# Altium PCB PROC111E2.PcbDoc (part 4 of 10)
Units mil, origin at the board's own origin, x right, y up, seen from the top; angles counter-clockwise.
Board outline 7700 x 2300 mil, 6 copper layers (Top Layer, GND 1, SIG 1, SIG 2, GND 2, Bottom Layer), stack 78.711 mil thick; 767 components, 596 nets, 2755 pads, 1578 vias.
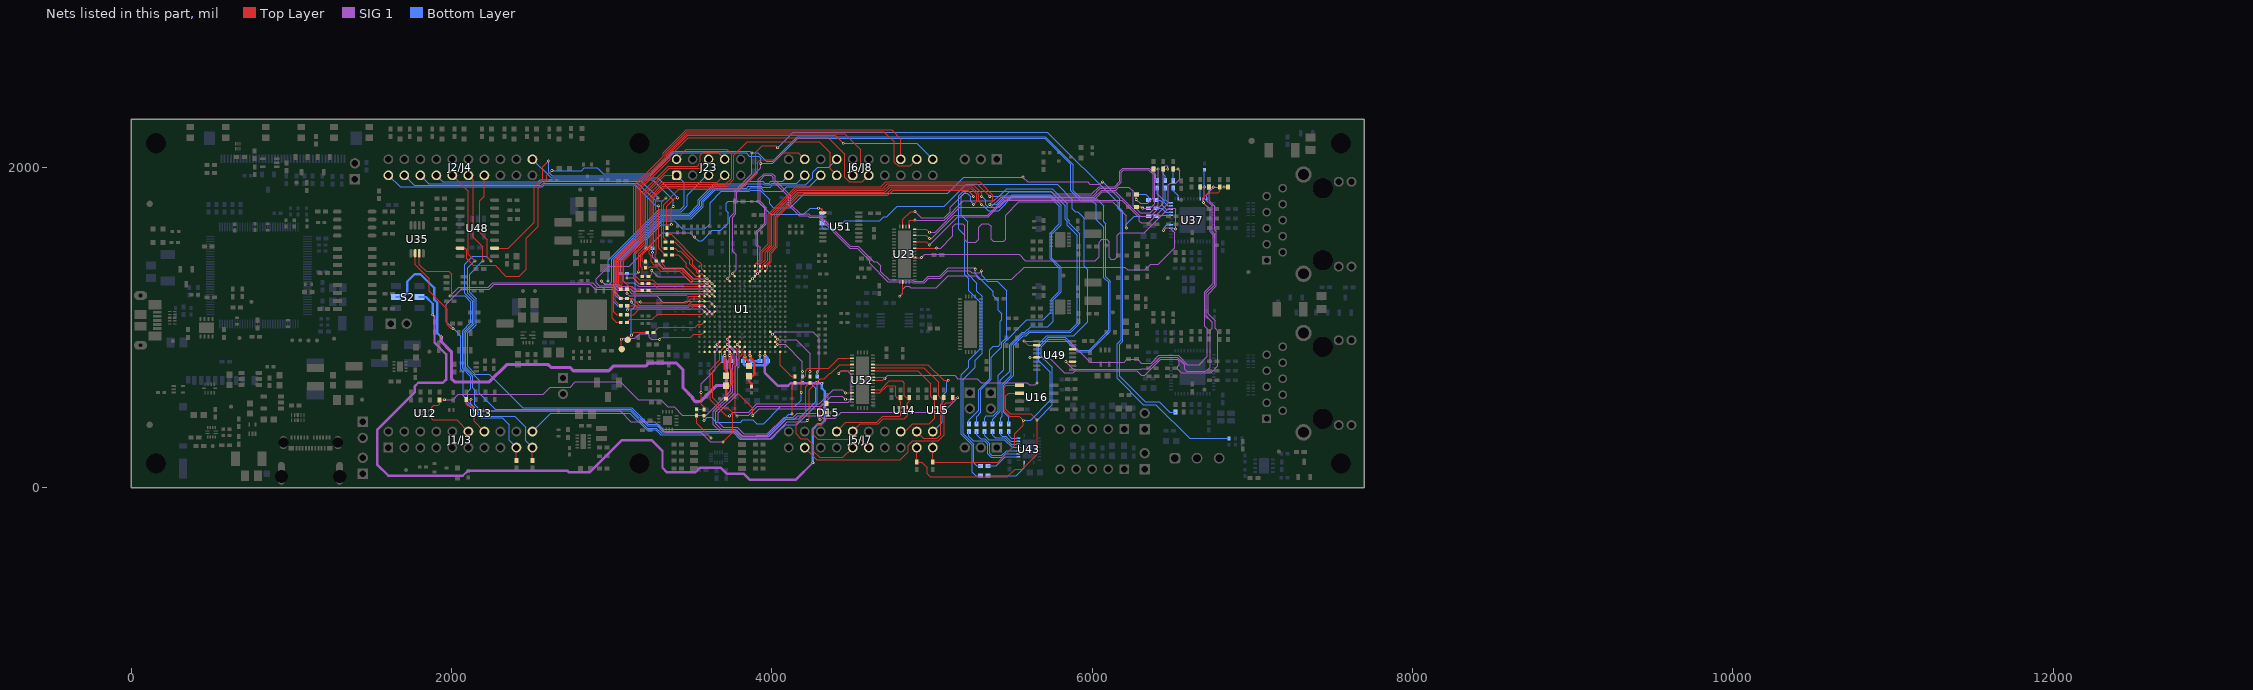
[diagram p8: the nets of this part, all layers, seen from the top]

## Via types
v1: diameter 18, hole 8, Top Layer to Bottom Layer, tented both sides, 1474 vias
v2: diameter 19.68, hole 7.87, Top Layer to Bottom Layer, tented both sides, 104 vias

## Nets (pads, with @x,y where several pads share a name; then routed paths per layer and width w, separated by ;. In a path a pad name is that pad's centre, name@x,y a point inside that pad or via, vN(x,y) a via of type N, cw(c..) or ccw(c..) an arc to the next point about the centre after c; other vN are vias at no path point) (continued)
AM263_ADC2_AIN2: U1.U10 U52.27 | length 1481.7
  Top Layer w5.3: U1.U10@3830.6,878.86 3813.63,861.89 3813.63,832.56 3785,803.94 3785,590 3880,495 v1(3880,450.85) ; v1(4417.1,713.38) 4432.77,729.06 U52.27@4500.04,729.06
  SIG 1 w4.75: v1(3880,450.85) 3921.63,492.49 4317.74,492.49 4357.02,531.77 4477.64,531.77 4495.75,549.88 4495.75,703.31 4470,729.06 4432.77,729.06 v1(4417.1,713.38)
AM263_ADC2_AIN2_SDFM0_CLK2: C93.1 J5/J7.68 U15.2 U15.9 U52.12 | length 879.5
  Top Layer w5.3: U52.12@4629.96,729.06 4909.46,729.06 4990,648.51 4990,570 4998.33,561.67 C93.1@5017.97,561.67 5015.48,559.18 5015.48,500.94 U15.9@5015.72,500.69 U15.2@5015.72,467.82 5015.72,432.26 4983.46,400 4879.37,400 4829.37,350 J5/J7.68@4804.17,350
AM263_ADC2_AIN3: C95.1 J5/J7.42 U1.T9 U15.5 U15.6 | length 3539.7
  Top Layer w5.3: J5/J7.42@4204.17,250 4280.97,173.2 4801.74,173.2 4852.06,223.52 4852.06,265 4880.13,293.06 5039.39,293.06 5074.77,328.45 U15.5@5074.77,467.82 ; v1(5160,561.03) 5159.36,561.67 C95.1@5128.54,561.67 5128.54,542.46 5114.41,528.33 5085.81,528.33 5074.77,517.29 U15.6@5074.77,500.69 ; U15.5@5074.77,467.82 U15.6@5074.77,500.69 ; U15.5@5074.77,467.82 U15.6@5074.77,500.69
  Top Layer w10: v1(3783.35,894.61) U1.T9@3799.1,910.35
  SIG 1 w4.75: v1(3783.35,894.61) 3794.9,883.06 3794.9,754.51 3785,744.61 3785,587.4 3665.68,468.08 3665.68,406.97 3696.4,376.25 3781.88,376.25 3823.5,334.63 3971.9,334.63 4077.01,439.74 4132.97,439.74 4157.22,463.99 4287.17,463.99 4318,433.16 4393.5,433.16 4431.09,470.75 5069.72,470.75 v1(5160,561.03)
AM263_ADC2_AIN4: U1.V9
AM263_ADC2_AIN5: U1.T8
AM263_ADC3_AIN0: C75.1 J1/J3.26 U1.U7 U12.5 U12.6 | length 2730.5
  Top Layer w5.3: v1(1954,548.33) C75.1@1924,548.33 1924,520.24 1916.62,512.86 1887.02,512.86 1874.37,500.2 U12.6@1874.37,480.91 U12.5@1874.37,448.04 1874.37,428.47 1880,422.84 2031.34,422.84 J1/J3.26@2104.17,350
  Top Layer w10: v1(3720.36,863.11) U1.U7@3736.11,878.86
  SIG 1 w4: v1@3720.36,862.49 v1(3720.36,863.11)
  SIG 1 w4.75: v1(1954,548.33) 2007.95,548.33 2041.97,582.35 2570,582.35 2615.14,627.49 2739.16,627.49 2771.67,660 3053.54,660 3163.53,550.01 3304.97,550.01 3350.45,504.53 3389.28,504.53 3441.06,452.75 3589.89,452.75 3741.83,604.69 3741.83,786.42 3751.48,796.07 3751.48,831.37 v1@3720.36,862.49
AM263_ADC3_AIN1: U1.U8 U52.36 | length 1226.9
  Top Layer w5.3: U1.U8@3767.61,878.86 3782.13,864.33 3782.13,829.46 3769.58,816.91 3769.58,458.43 v1(3781.85,446.17) ; v1(4458.39,551.89) U52.36@4500.04,551.89
  SIG 1 w4.75: v1(3781.85,446.17) 3788.43,452.75 3854.68,452.75 3908.66,506.74 4306.74,506.74 4371.14,571.14 4439.14,571.14 v1(4458.39,551.89)
AM263_ADC3_AIN1_MCAN1_TX: C86.1 J5/J7.64 U14.2 U14.9 U52.5 | length 812.1
  Top Layer w5.3: J5/J7.64@4404.17,350 4462.03,407.86 4653.57,407.86 4690.71,445 4799.14,445 4805.31,451.17 U14.2@4805.31,467.68 U14.9@4805.31,500.55 4805.31,533.2 4802.11,536.4 C86.1@4802.11,561.53 4780.42,561.53 4772.38,569.58 4772.38,630 4765.84,636.54 4719.02,636.54 4673.74,591.26 U52.5@4629.96,591.26
AM263_ADC3_AIN2: U1.T7 U52.25 | length 1796
  Top Layer w5.3: v1(4220,419.26) 4231.5,430.75 4231.5,611.09 4300.41,680 4326.38,680 4359.76,713.38 4367,713.38 4422.04,768.43 U52.25@4500.04,768.43
  Top Layer w10: v1(3720.36,894.61) U1.T7@3736.11,910.35
  SIG 1 w4.75: v1(3720.36,894.61) 3720.36,893.05 3765.73,847.67 3765.73,776.62 3756.08,766.97 3756.08,598.79 3634.18,476.89 3634.18,393.18 3679.62,347.75 3770.07,347.75 3811.7,306.13 3989.63,306.13 4094.74,411.24 4211.98,411.24 v1(4220,419.26)
AM263_ADC3_AIN2_SDFM0_D3: C94.1 J5/J7.69 U15.4 U15.7 U52.13 | length 984.4
  Top Layer w5.3: U52.13@4629.96,748.74 4948.18,748.74 5040.31,656.61 5040.31,573.23 5051.87,561.67 C94.1@5073,561.67 5073,538 5055.09,520.09 U15.7@5055.09,500.69 U15.4@5055.09,467.82 5055.09,331.25 5032.8,308.96 4945.21,308.96 J5/J7.69@4904.17,350
AM263_ADC3_AIN3: C96.1 D15.2 J5/J7.46 U1.R7 | length 2133.9
  Top Layer w5.3: v1(4300.31,423.62) 4300.31,508.74 4317.89,526.31 C96.1@4339.72,526.31 4339.72,467.6 D15.2@4338.78,466.66 4338.78,423.78 4310,395 4282.16,395 4257.41,370.25 4257.41,329.77 4284.26,302.93 4551.24,302.93 J5/J7.46@4604.17,250
  Top Layer w10: v1(3720.36,926.1) U1.R7@3736.11,941.85
  SIG 1 w4: v1(3720.36,926.1) 3736.86,909.61 3736.86,888.39 3779.98,845.27
  SIG 1 w4.75: 3779.98,845.27 3779.98,764.98 3770.33,755.33 3770.33,592.89 3650,472.55 3650,397.52 3685.52,362 3775.98,362 3817.6,320.38 3983.73,320.38 4088.84,425.49 4138.88,425.49 4162.23,448.84 4275.09,448.84 v1(4300.31,423.62)
AM263_ADC3_AIN4: U1.V8
AM263_ADC3_AIN5: U1.U9
AM263_ADC4_AIN0: C81.1 J1/J3.27 U1.U6 U13.1 U13.10 | length 2712.5
  Top Layer w5.3: v1@2120,548.85 C81.1@2090,548.85 2090,520 2098.65,511.35 2124.65,511.35 2140.63,495.36 U13.10@2140.63,481.44 U13.1@2140.63,448.56 2140.63,413.54 J1/J3.27@2204.17,350 ; v1(3694.17,285) 3755.86,346.68 3755.86,466.58 3722.44,500 3690,500 3628.99,561.01 3628.99,727.74 3687.64,786.39 3687.64,861.89 U1.U6@3704.61,878.86
  SIG 1 w4.75: v1(2120,548.85) 2120,522.52 2163.5,479.02 3050.98,479.02 3118.98,411.02 3267.48,411.02 3334,344.5 3555,344.5 3614.5,285 v1(3694.17,285)
AM263_ADC4_AIN1: U1.V5 U52.34 | length 1326.7
  Top Layer w5.3: U1.V5@3673.12,847.36 3673.12,797.41 3613.09,737.38 3613.09,549.79 3714.78,448.1 v1(3735,448.1) ; v1(4458.39,591.26) U52.34@4500.04,591.26
  SIG 1 w4.75: v1(3735,448.1) 3758.61,471.71 3853.48,471.71 3906.06,524.29 4295.27,524.29 4381.49,610.51 4439.14,610.51 v1(4458.39,591.26)
AM263_ADC4_AIN1_LIN1_RXD: C87.1 J5/J7.65 U14.4 U14.7 U52.6 | length 837
  Top Layer w5.3: J5/J7.65@4504.17,350 4551.43,397.26 4662,397.26 4696.12,431.38 4826.04,431.38 4844.69,450.03 U14.4@4844.69,467.68 U14.7@4844.69,500.55 4844.69,527.99 4856.7,540 C87.1@4856.7,561.53 4838.47,561.53 4827.2,572.8 4827.2,651.1 4812.48,665.82 4732.61,665.82 4677.73,610.94 U52.6@4629.96,610.94
AM263_ADC4_AIN2: U1.V4
AM263_ADC4_AIN3: U1.U5
AM263_ADC4_AIN4: U1.V3
AM263_ADC4_AIN5: U1.U4
AM263_ADC_CAL0: U1.U16
AM263_ADC_CAL1: U1.T15
AM263_ADC_VREFHI_G01: C77.1 C79.1 C80.1 S2.2 U1.V10 U1.V14 | length 5924.9
  Top Layer w15: U1.V10@3830.6,847.36 3831.11,846.85 v1(3831.11,816.77) 3831.11,810.33 3830.6,809.82 3855,785.41 C77.1@3855,758.87 ; v1(3956.58,825) U1.V14@3956.58,847.36
  SIG 1 w15: v1(1881.26,1079.09) 1892.09,1068.26 1892.09,905.2 1964.73,832.57 1964.73,674.26 1944.82,654.35 1790.45,654.35 1770,633.9 1770,596.59 1533.7,360.28 1533.7,144.46 1604.73,73.43 2068.73,73.43 2099.68,104.37 2723.63,104.37 2733.12,94.88 2860.51,94.88 3060.41,294.78 3250,294.78 3316.5,228.28 3316.5,123.5 3344.87,95.13 3520.66,95.13 3550.31,124.78 3678.51,124.78 3716.07,87.22 3822.14,87.22 3859.35,50 4149.88,50 4254.88,155 v1(4255,155) ; v1(3956.58,825) 3956.01,824.43 3956.01,822.3 3955.63,821.92 3955.63,719.49 3956.05,719.06 3956.05,716.42 4035.38,637.09 4101.11,637.09 4115.3,651.28 v1(4311.54,651.28)
  Bottom Layer w15: S2.2@1797.54,1190 1839.19,1190 1881.26,1147.93 v1(1881.26,1079.09) ; v1(3831.11,816.77) 3823.14,808.8 3823.14,769.23 3829.62,762.75 3958.56,762.75 3972.24,776.43 C80.1@3972.24,789.94 3972.24,809.34 v1(3956.58,825) ; v1(4255,155) 4255,365.72 4285.17,395.89 4307.05,395.89 4329.69,418.53 4329.69,601.57 4311.54,619.71 v1(4311.54,651.28)
AM263_ADC_VREFHI_G2: C76.1 C78.1 S2.5 U1.V6 | length 3381
  Top Layer w15: U1.V6@3704.61,847.36 v1(3704.61,825) 3704.61,742.32 3713.32,733.62 3713.32,698.14 C76.1@3713.17,698
  SIG 1 w8: 3704.49,800.8 3707.05,798.24 ; v1@3704.49,824.87 v1(3704.61,825)
  SIG 1 w20: v1(1935,940) 1935,912.11 1998.13,848.98 1998.13,680.65 2018.77,660 2234.9,660 2342.91,768.02 2602.89,768.02 2620.91,750 2739.93,750 2759.93,730 2979.51,730 3008.2,758.68 3210.94,758.68 3230.34,778.09 3401.52,778.09 3444.13,735.48 3444.13,622.47 3504.51,562.09 3504.51,552.94 3520.25,537.2 3550.76,537.2 3650.66,637.09 3700.33,637.09 3715.62,652.38 3715.62,789.67 3707.05,798.24 ; 3704.49,800.8 v1@3704.49,824.87
  Bottom Layer w15: S2.5@1651.87,1190 1697.96,1190 1721.8,1213.85 1721.8,1286.8 1767.62,1332.62 1805,1332.62 1890.03,1247.59 1890.03,1174.7 1910,1154.73 1910,965 v1(1935,940) ; C78.1@3696.74,789.94 3696.74,817.13 v1(3704.61,825)
AM263_ADC_VREFLO_G01: C77.2 C79.2 C80.2 R44.2 U1.V11 U1.V13 | length 413.8
  Top Layer w4: v1(3925.09,825) U1.V13@3925.09,847.36
  Top Layer w15: U1.V11@3862.09,847.36 v1(3862.09,825) 3862.67,824.43 3862.67,812.33 3889.07,785.92 3889.07,707.15 3877.8,695.88 C77.2@3855,695.88 3855,666.5 3872.63,648.88 R44.2@3872.63,631.2
  Bottom Layer w15: v1(3862.09,825) 3862.09,824.19 3868.43,817.85 C79.2@3868.43,789.94 C80.2@3925,789.94 3925,824.91 v1(3925.09,825)
AM263_ADC_VREFLO_G2: C76.2 C78.2 R307.2 U1.V7 | length 362.5
  Top Layer w15: R307.2@3713.62,555 3713.17,555.45 C76.2@3713.17,635.01 3737.59,635.01 3748.83,646.26 3748.83,733.91 3736.11,746.64 v1@3736.11,822.29 ; v1(3736.11,825) U1.V7@3736.11,847.36
  Bottom Layer w15: v1(3736.11,825) 3743.98,817.13 C78.2@3743.98,789.94
AM263_ATESTV0: U1.U3
AM263_ATESTV1: U1.V2
AM263_BP_MUX_SEL_GPIO63: R298.2 R300.2 U1.G4 U51.1 U52.9 U52.10 | length 7040.3
  Top Layer w5.3: v1(4291.03,1744.24) 4306.84,1744.24 4317.8,1733.28 U51.1@4317.8,1717.48 ; U52.9@4629.96,670 4693.01,670 v1(4705,681.99) 4697.31,689.68 U52.10@4629.96,689.68
  Top Layer w10: v1(3625.87,1209.57) U1.G4@3641.62,1193.82
  SIG 1 w4: 3518.68,1226.06 3609.38,1226.06 v1(3625.87,1209.57)
  SIG 1 w4.75: v1(3515.64,1564.46) 3488.69,1591.41 3317.97,1591.41 3109.37,1382.8 2979.62,1382.8 2902.31,1305.49 2902.31,1278.83 2921.14,1260 3024.5,1260 3042.5,1242 3116.39,1242 3132.32,1226.06 3518.68,1226.06
  SIG 1 w5.3: v1(4705,681.99) 4723.17,700.16 5141.38,700.16 5161.5,680.04 5281.04,680.04 5305.58,655.5 5592.71,655.5 5605.21,643 5644.31,643 v1(5654.39,653.09)
  Bottom Layer w5.3: v1(3515.64,1564.46) 3538.74,1541.35 3563.03,1541.35 3627.8,1606.12 3680.51,1606.12 3726.52,1652.14 3726.52,1715.86 3713.62,1728.77 3713.62,1775.16 3725.58,1787.12 3911.05,1787.12 3991.69,1706.48 4199.68,1706.48 4237.44,1744.24 v1(4291.03,1744.24) 4301.08,1744.24 4312.89,1732.43 R298.2@4312.89,1715.49 R300.2@4312.89,1652.52 4312.89,1626.91 4323,1616.79 4405.75,1616.79 4453.96,1665 4672.04,1665 4697.54,1690.5 4717.5,1690.5 4783.54,1756.54 5075.54,1756.54 5212,1893 5782.5,1893 5876.5,1799 5876.5,1741.5 5894,1724 5908.74,1724 5951,1681.74 5951,1383.57 5972.85,1361.72 5972.85,1035.35 5885.7,948.2 5714.61,948.2 5655,888.59 5655,653.69 v1(5654.39,653.09)
AM263_CAN_STB_GPIO51: R248.2 U1.D1 | length 6072.1
  Top Layer w4: 3515.64,1288.31 U1.D1@3547.13,1288.31
  Top Layer w5.3: 3515.64,1288.31 3507.89,1288.31 3435.14,1361.06 3322.44,1361.06 3291,1392.5 3263,1392.5 3246.28,1409.22 3246.28,1447.41 3234.85,1458.85 3234.85,1478.14 3261.6,1504.89 3261.6,1810.22 3323.68,1872.3 3801.74,1872.3 3899.52,1970.08 3899.52,2094.24 3940.28,2135 4022.68,2135 v1(4035.32,2122.36)
  Bottom Layer w5.3: v1(4035.32,2122.36) 4132.97,2220 5720,2220 6161.25,1778.75 6161.25,1740.07 6179.88,1721.45 6179.88,922.38 6155,897.5 6155,683.66 6320,518.66 6397.07,518.66 6608.49,307.24 R248.2@6855,307.24
AM263_CLKOUT0: R4.2 R118.1 TP1.1 | length 5760.5
  Top Layer w5.3: TP1.1@3098.87,922.75 3098.87,928.07 v1(3122.32,951.52) 3139.85,969.06 R4.2@3221.22,969.06
  SIG 1 w4.75: v1(5567.49,1938.61) 5596.85,1909.25 5970.75,1909.25 5984.25,1895.75 6051.33,1895.75 v1(6065,1909.42)
  Bottom Layer w5.3: v1(3122.32,951.52) 3122.32,1108.82 3144.52,1131.02 3144.52,1491.6 3317.93,1665 3389.12,1665 3439.12,1615 3580,1615 3613.9,1648.9 3613.9,1778.89 3684.53,1849.52 3858.86,1849.52 3867.31,1857.97 3925.21,1857.97 3985,1798.18 3985,1773.13 4009.25,1748.88 4114.83,1748.88 4204.88,1838.92 5097.92,1838.92 5197.61,1938.61 v1(5567.49,1938.61) ; v1(6065,1909.42) 6171.85,1802.57 6171.85,1744.46 6190.48,1725.84 6190.48,912.98 6171.85,894.35 6171.85,695.04 6330,536.89 6417.03,536.89 6482.54,471.38 R118.1@6520,471.38
AM263_CLKOUT0_R: R4.1 U1.M2 | length 345.9
  Top Layer w4: 3539.45,1020.59 3562.88,1020.59 U1.M2@3578.63,1036.34
  Top Layer w5.3: R4.1@3260.59,969.06 3293.06,1001.54 3520.39,1001.54 3539.45,1020.59
AM263_DAC_OUT1: J1/J3.30 R45.1 | length 1403.7
  Top Layer w5.3: R45.1@3528.72,450.24 3528.72,400.34 v1(3618.83,310.23)
  Bottom Layer w5.3: J1/J3.30@2504.17,350 2619.17,465 3112.73,465 3216.45,361.28 3273.73,361.28 3304.51,330.5 3598.56,330.5 v1(3618.83,310.23)
AM263_DAC_OUT2: R3.1 U52.23 | length 1253.4
  Top Layer w5.3: v1(3575.19,418.7) R3.1@3575.19,448.84 ; v1(4182.78,594.53) 4181.82,595.49 4181.82,670.64 4209.52,698.35 4209.52,729.88 4223.55,743.91 4353.02,743.91 4416.91,807.8 U52.23@4500.04,807.8
  Bottom Layer w5.3: v1(3575.19,418.7) 3594.71,438.22 3622.55,438.22 3651.67,409.1 3803.38,409.1 3818.8,424.52 3880.9,424.52 3905.95,399.46 3948.02,399.46 4054.9,506.35 4142.26,506.35 4182.08,546.17 4182.08,593.83 v1(4182.78,594.53)
AM263_DAC_OUT2_SDFM0_CLK3: J5/J7.70 U52.14 | length 871.6
  Top Layer w5.3: U52.14@4629.96,768.43 4973.69,768.43 5071.52,670.59 v1(5100.56,670.59)
  Bottom Layer w5.3: J5/J7.70@5004.17,350 5063.33,409.15 5063.33,573.33 5092.52,602.52 5092.52,661.13 5100.56,669.16 v1(5100.56,670.59)
AM263_DAC_OUT_R: R3.2 R45.2 U1.T5 | length 523.2
  Top Layer w5.3: R45.2@3528.72,489.61 3573.8,489.61 R3.2@3574.55,488.85 ; v1(3557.81,594.15) 3557.81,521.62 3574.55,504.87 R3.2@3574.55,488.85 ; R3.2@3575.19,488.21 R3.2@3574.55,488.85
  Top Layer w10: v1(3657.37,894.61) U1.T5@3673.12,910.35
  SIG 1 w4: 3645,815.87 3645,848.34 3657.37,860.71 v1(3657.37,894.61)
  SIG 1 w4.75: v1(3557.81,594.15) 3557.81,649.18 3645,736.37 3645,815.87
AM263_EPWM0_A: J2/J4.11 R46.1 | length 1229.8
  Top Layer w5.3: R46.1@3344.16,1620.17 3344.16,1756.66 3396.77,1809.27 v1(3410.06,1809.27)
  Bottom Layer w5.3: J2/J4.11@2504.17,2050 2620.48,1933.69 3285.64,1933.69 v1(3410.06,1809.27)
AM263_EPWM0_A_R: R46.2 U1.B2 | length 343.2
  Top Layer w4: 3536.77,1414.29 3537.52,1413.54 3539.53,1413.54 3547.44,1405.64 3547.58,1405.64 3562.88,1390.34 3562.88,1367.05 U1.B2@3578.63,1351.3
  Top Layer w5.3: R46.2@3344.16,1580.8 3370.27,1580.8 3536.77,1414.29
AM263_EPWM0_B: J6/J8.59 R47.1 | length 1309.3
  Top Layer w5.3: R47.1@3335.32,1534 3335.32,1548.68 3323,1561 3323,1766.4 3418.3,1861.7 3806.13,1861.7 3910.48,1966.05 3910.48,2032.84 3926.33,2048.69 4024.01,2048.69 4066.36,2091.04 4163.14,2091.04 J6/J8.59@4204.17,2050
AM263_EPWM0_B_R: R47.2 U1.B1 | length 264.5
  Top Layer w4: 3515.64,1382.8 U1.B1@3547.13,1351.3
  Top Layer w5.3: R47.2@3374.69,1534 3392.43,1534 3506.5,1419.93 3506.5,1391.93 3515.64,1382.8
AM263_EPWM1_A: J2/J4.37 R48.1 | length 1962.1
  Top Layer w5.3: v1(3372,1642) 3372,1744.5 v1(3383,1755.5)
  Bottom Layer w5.3: J2/J4.37@1904.17,1950 1945.21,1908.96 2540,1908.96 2554.13,1923.09 3253.91,1923.09 3383,1794 v1(3383,1755.5) v1@3383,1753.5 ; R48.1@3215,1495 3215,1547.08 3309.92,1642 v1(3372,1642)
AM263_EPWM1_A_R: R48.2 U1.D3 | length 475.4
  Top Layer w10: v1(3594.38,1304.06) U1.D3@3610.12,1288.31
  SIG 1 w4: 3515.64,1304.06 v1(3594.38,1304.06)
  SIG 1 w4.75: v1(3254.37,1466.94) 3254.37,1436.87 3321.24,1370 3442.05,1370 3507.99,1304.06 3515.64,1304.06
  Bottom Layer w5.3: v1(3254.37,1466.94) R48.2@3254.37,1495
AM263_EPWM1_B: J2/J4.38 R49.1 | length 1962.2
  Top Layer w5.3: R49.1@3277.82,1415.5 3277.82,1431.37 3271.87,1437.32 3271.87,1453 3278.62,1459.75 3278.62,1725.38 3272.69,1731.31 3272.69,1793.93 3288.03,1809.27 v1(3288.27,1809.27)
  Bottom Layer w5.3: J2/J4.38@1804.17,1950 1855.81,1898.36 2550,1898.36 2564.13,1912.49 3185.05,1912.49 v1(3288.27,1809.27)
AM263_EPWM1_B_R: R49.2 U1.D2 | length 327
  Top Layer w4: 3515.64,1305.38 3561.56,1305.38 U1.D2@3578.63,1288.31
  Top Layer w5.3: R49.2@3317.19,1415.5 3317.19,1393.51 3336.94,1373.76 3437.43,1373.76 3505.81,1305.38 3515.64,1305.38
AM263_EPWM2_A: J2/J4.39 R50.1 | length 2066.5
  Top Layer w5.3: R50.1@3335.32,1493.5 3318.5,1493.5 3311.86,1500.14 3311.86,1782.87 v1(3338.27,1809.27)
  Bottom Layer w5.3: J2/J4.39@1704.17,1950 1766.41,1887.76 2560,1887.76 2574.13,1901.89 3160.45,1901.89 3272.6,1789.75 3318.74,1789.75 v1(3338.27,1809.27)
AM263_EPWM2_A_R: R50.2 U1.C2 | length 293.2
  Top Layer w4: 3529.96,1345.78 3540.19,1335.55 3562.88,1335.55 U1.C2@3578.63,1319.8
  Top Layer w5.3: R50.2@3374.69,1493.5 3396.05,1493.5 3413.55,1476 3429.32,1476 3486.25,1419.07 3486.25,1396.25 3529.96,1352.54 3529.96,1345.78
AM263_EPWM2_B: J2/J4.40 R51.1 | length 2099.5
  Top Layer w5.3: v1(3292.21,1759.27) 3292.21,1494.79 3333.5,1453.5 R51.1@3335.32,1453.5
  Bottom Layer w5.3: J2/J4.40@1604.17,1950 1677.01,1877.16 2564.39,1877.16 2578.52,1891.29 3142.38,1891.29 3274.4,1759.27 v1@3288.27,1759.27
AM263_EPWM2_B_R: R51.2 U1.C1 | length 241.8
  Top Layer w5.3: R51.2@3374.69,1453.5 3414.01,1453.5 3465.77,1401.75 3465.77,1377.91 3523.87,1319.8 U1.C1@3547.13,1319.8
AM263_EPWM3_A: J6/J8.77 R52.1 | length 1974
  Top Layer w5.3: R52.1@3210.5,1411.61 3195.56,1411.61 3190.98,1416.19 3190.98,1452.49 3251,1512.51 3251,1814.61 3319.29,1882.9 3717.56,1882.9 3761.17,1926.51 3761.17,2075 3846.17,2160 4295,2160 4363.14,2091.86 4363.14,1991.04 J6/J8.77@4404.17,1950
AM263_EPWM3_A_R: R52.2 U1.E2 | length 420.3
  Top Layer w4: 3515.64,1272.56 3562.88,1272.56 U1.E2@3578.63,1256.81
  Top Layer w5.3: R52.2@3210.5,1372.24 3230.24,1372.24 3235.5,1377.5 3276,1377.5 3304,1349.5 3425.03,1349.5 3501.97,1272.56 3515.64,1272.56
AM263_EPWM3_B: J6/J8.78 R53.1 | length 1578.6
  Bottom Layer w5.3: R53.1@3055.32,1341.34 3055.32,1417.38 3317.69,1679.75 3495.49,1679.75 3570.48,1754.74 3570.48,1783.55 3647.05,1860.12 3854.47,1860.12 3865.8,1871.46 3929.38,1871.46 3948.98,1851.85 4064.19,1851.85 4092.34,1880 4234.17,1880 J6/J8.78@4304.17,1950
AM263_EPWM3_B_R: R53.2 U1.E3 | length 564.1
  Top Layer w10: v1(3594.38,1272.56) U1.E3@3610.12,1256.81
  SIG 1 w4: 3515.64,1272.56 v1(3594.38,1272.56)
  SIG 1 w4.75: v1(3094.69,1309.45) 3132.55,1309.45 3169.44,1272.56 3515.64,1272.56
  Bottom Layer w5.3: v1(3094.69,1309.45) R53.2@3094.69,1336.34
AM263_EPWM9_A: J6/J8.75 R9.1 | length 2465.8
  Top Layer w5.3: R9.1@3055.09,1238.11 3055.09,1259.45 3064.56,1268.92 3064.56,1420.53 3180.1,1536.07 3180.1,1867.1 3363.9,2050.9 3363.9,2073.4 3475.85,2185.35 4351.06,2185.35 4455.62,2080.8 4455.62,1936.68 4483.33,1908.96 4563.14,1908.96 J6/J8.75@4604.17,1950
AM263_EPWM9_A_R: R9.2 U1.G1 | length 471
  Top Layer w4: 3515.64,1193.82 U1.G1@3547.13,1193.82
  Top Layer w5.3: R9.2@3094.46,1238.11 3113.89,1238.11 3149.38,1202.62 3465.6,1202.62 3474.41,1193.82 3515.64,1193.82
AM263_EPWM9_B: J6/J8.76 R12.1 | length 2579.5
  Top Layer w5.3: R12.1@3055.09,1135.05 3053.12,1135.05 3022.15,1166.01 3022.15,1256.7 3042.4,1276.95 3042.4,1428.35 3158.9,1544.85 3158.9,1875.88 3342.7,2059.68 3342.7,2082.18 3469.91,2209.39 4453.93,2209.39 4460.46,2202.85 4463.32,2200 4553.32,2110 4553.32,1999.15 J6/J8.76@4504.17,1950
AM263_EPWM9_B_R: R12.2 U1.J2 | length 501.2
  Top Layer w4: 3515.64,1145 3564.46,1145 U1.J2@3578.63,1130.83
  Top Layer w5.3: R12.2@3094.46,1135.05 3144.95,1135.05 3153.47,1126.53 3481.53,1126.53 3500,1145 3515.64,1145
AM263_EPWM11_A: J6/J8.51 R13.1 | length 2801.9
  Top Layer w5.3: R13.1@3055.09,1181.64 3053.12,1181.64 3032.75,1202.01 3032.75,1252.31 3053,1272.56 3053,1423.96 3169.5,1540.46 3169.5,1871.49 3353.3,2055.29 3353.3,2077.79 3474.3,2198.79 4396.21,2198.79 v1(4445,2150)
  Bottom Layer w5.3: v1(4445,2150) 4904.17,2150 J6/J8.51@5004.17,2050
AM263_EPWM11_A_R: R13.2 U1.H1 | length 481.5
  Top Layer w4: 3515.64,1162.32 U1.H1@3547.13,1162.32
  Top Layer w5.3: R13.2@3094.46,1181.64 3125.36,1181.64 3169.87,1137.13 3477.14,1137.13 3502.33,1162.32 3515.64,1162.32
AM263_EPWM11_B: J6/J8.52 R99.1 | length 2978.9
  Top Layer w5.3: R99.1@3053.12,1079.62 3030.38,1079.62 3011.55,1098.45 3011.55,1261.09 3031.8,1281.34 3031.8,1432.74 3148.3,1549.24 3148.3,1880.27 3332.1,2064.07 3332.1,2086.57 3468.62,2223.09 4698.52,2223.09 4763.14,2158.47 4763.14,2033 4787.17,2008.96 4864.48,2008.96 4904.17,2048.66 J6/J8.52@4904.17,2050
AM263_EPWM11_B_R: R99.2 U1.J1 | length 473.9
  Top Layer w4: 3515.64,1130.83 U1.J1@3547.13,1130.83
  Top Layer w5.3: R99.2@3094.46,1079.62 3135.36,1079.62 3167.91,1112.16 3491.53,1112.16 3510.19,1130.83 3515.64,1130.83
AM263_EPWM12_A: J6/J8.53 R280.1 | length 2922.6
  Top Layer w5.3: R280.1@3055.09,1031.94 3027.09,1031.94 3000.95,1058.08 3000.95,1265.48 3021.2,1285.73 3021.2,1437.13 3137.7,1553.63 3137.7,1884.66 3321.5,2068.46 3321.5,2090.96 3464.22,2233.69 4747.04,2233.69 4804.17,2176.55 J6/J8.53@4804.17,2050
AM263_EPWM12_A_R: R280.2 U1.K2 | length 512.1
  Top Layer w4: 3515.64,1083.58 3562.88,1083.58 U1.K2@3578.63,1099.33
  Top Layer w5.3: R280.2@3094.46,1031.94 3112.52,1050 3252.62,1050 3286.2,1083.58 3515.64,1083.58
AM263_EPWM12_B: J6/J8.57 R281.1 | length 1858.4
  Bottom Layer w5.3: R281.1@3055.32,1239.6 3032.98,1261.93 3032.98,1410.04 3313.3,1690.35 3491.1,1690.35 3559.88,1759.13 3559.88,1787.94 3642.66,1870.72 3841.76,1870.72 3853.09,1882.06 3933.77,1882.06 3939.13,1876.69 3987.7,1876.69 4001.91,1890.9 4211.79,1890.9 4254.82,1933.93 4254.82,1970 4284.82,2000 4354.17,2000 J6/J8.57@4404.17,2050
AM263_EPWM12_B_R: R281.2 U1.J4 | length 612.5
  Top Layer w10: v1(3625.87,1146.57) U1.J4@3641.62,1130.83
  SIG 1 w4: 3515.64,1162.63 3609.82,1162.63 v1(3625.87,1146.57)
  SIG 1 w4.75: v1(3094.46,1211) 3108.26,1197.2 3279.76,1197.2 3318.53,1158.44 3453.95,1158.44 3458.15,1162.63 3515.64,1162.63
  Bottom Layer w5.3: v1(3094.46,1211) 3094.69,1211.23 R281.2@3094.69,1239.6
AM263_EPWM13_A: J6/J8.79 R59.1 | length 1681.2
  Bottom Layer w5.3: R59.1@3055.32,1181.51 3040.47,1181.51 3022.38,1199.6 3022.38,1414.43 3308.91,1700.95 3486.71,1700.95 3549.28,1763.52 3549.28,1792.33 3642.74,1885.8 3832,1885.8 3842.6,1896.4 3943.72,1896.4 3950.24,1889.88 3985.9,1889.88 3997.52,1901.5 4155.67,1901.5 J6/J8.79@4204.17,1950
AM263_EPWM13_A_R: R59.2 U1.K4 | length 602
  Top Layer w10: v1(3625.87,1083.58) U1.K4@3641.62,1099.33
  SIG 1 w4.75: v1(3121.5,1157.83) 3144.33,1135 3574.46,1135 v1(3625.87,1083.58)
  Bottom Layer w5.3: R59.2@3094.69,1181.51 3111.49,1181.51 3121.5,1171.5 v1(3121.5,1157.83)
AM263_EPWM13_B: J6/J8.80 R60.1 | length 1655.1
  Bottom Layer w5.3: R60.1@3056.12,1135.05 3036.98,1135.05 3011.78,1160.25 3011.78,1423.57 3299.76,1711.55 3482.32,1711.55 3538.68,1767.91 3538.68,1796.72 3638.35,1896.4 3827.61,1896.4 3843.32,1912.1 3943.01,1912.1 3954.63,1900.48 3981.51,1900.48 3993.13,1912.1 4066.27,1912.1 J6/J8.80@4104.17,1950
AM263_EPWM13_B_R: R60.2 U1.K3 | length 564.1
  Top Layer w10: v1(3594.38,1083.58) U1.K3@3610.12,1099.33
  SIG 1 w4.75: v1(3097.46,1108.15) 3106.94,1117.63 3560.33,1117.63 v1(3594.38,1083.58)
  Bottom Layer w5.3: v1(3097.46,1108.15) R60.2@3097.46,1135.05
AM263_EPWM14_A: J2/J4.35 R282.1 | length 3769.6
  Top Layer w5.3: J2/J4.35@2104.17,1950 2135.38,1918.8 2135.38,1563.41 2195,1503.78 v1(2195,1415.64) ; v1(4125,458.99) 4125,637 R282.1@4143,655
  Bottom Layer w5.3: v1(2195,1415.64) 2111.44,1332.08 2111.44,1221.08 2152,1180.52 2152,1018.21 2099.19,965.4 2099.19,757.06 2147.28,708.97 2235.3,708.97 2444.41,499.86 3122.84,499.86 3227.09,395.61 3288.59,395.61 3321.3,362.9 3768.39,362.9 3808.74,322.55 3896.73,322.55 3901.79,327.6 3972.6,327.6 4103.99,458.99 v1(4125,458.99)
AM263_EPWM14_A_R: R282.2 U1.V17 | length 204.1
  Top Layer w5.3: U1.V17@4051.07,847.36 4051.07,763.99 4120.69,694.37 R282.2@4143,694.37
AM263_EPWM14_B: J2/J4.36 R283.1 | length 4000.5
  Top Layer w5.3: J2/J4.36@2004.17,1950 2104.17,1850 2104.17,1456.47 v1(2145,1415.64)
  Bottom Layer w5.3: v1(2145,1415.64) 2100.84,1371.48 2100.84,1214.16 2141.4,1173.6 2141.4,1022.6 2088.59,969.79 2088.59,752.67 2171.32,669.93 2171.32,589.92 2271.98,489.26 3118.45,489.26 3222.71,385 3283.51,385 3316.21,352.3 3763.99,352.3 3804.35,311.95 3901.12,311.95 3906.18,317 3976.99,317 4090,430 4167.53,430 4272.54,535.02 4272.54,620.15 4237.69,655 R283.1@4190,655
AM263_EPWM14_B_R: R283.2 U1.T16 | length 313.8
  Top Layer w10: U1.T16@4019.57,910.35 v1(4035.32,894.61)
  SIG 1 w4.75: v1(4035.32,894.61) 4081.83,894.61 4190,786.43 v1(4190,724.36)
  Bottom Layer w5.3: R283.2@4190,694.37 v1(4190,724.36)
AM263_EPWM15_A: J2/J4.34 R284.1 | length 4169.5
  Top Layer w5.3: J2/J4.34@2204.17,1950 2204.17,1819.87 2175,1790.7 2175,1593.86 2220.89,1547.97 2220.89,1439.75 v1(2245,1415.64)
  Bottom Layer w5.3: v1(2245,1415.64) 2217.11,1443.54 2131.42,1443.54 2081.83,1393.95 2081.83,1213.17 2130.8,1164.2 2130.8,1026.99 2077.99,974.18 2077.99,748.28 2130.48,695.79 2130.48,622.41 2145,607.89 2145,517.39 2183.73,478.66 3114.06,478.66 3220.85,371.88 3278.12,371.88 3308.3,341.7 3759.6,341.7 3799.96,301.35 3905.52,301.35 3910.57,306.4 3998.57,306.4 4042.93,350.77 4084.9,392.74 4154.2,392.74 4283.14,521.68 4283.14,654.64 R284.1@4282.78,655
AM263_EPWM15_A_R: R284.2 U1.P15 | length 580
  Top Layer w10: U1.P15@3988.08,973.35 v1(4003.83,957.6)
  SIG 1 w4: v1(4003.83,957.6) 4018.83,972.6 4041.54,972.6
  SIG 1 w4.75: 4041.8,972.86 4255.88,972.86 4295,933.74 4295,734.48 v1(4282.93,722.41)
  Bottom Layer w5.3: R284.2@4282.93,694.37 v1(4282.93,722.41)
AM263_EPWM15_B: J5/J7.45 R285.1 | length 818.3
  Top Layer w5.3: R285.1@4236.47,655 4210.42,628.95 4210.42,462.84 4150,402.43 4150,335 4180,305 4219.59,305 4258.64,265.95 4258.64,227.31 4296.85,189.1 4443.27,189.1 J5/J7.45@4504.17,250
AM263_EPWM15_B_R: R285.2 U1.R16 | length 404.4
  Top Layer w5.3: R285.2@4236.47,696.32 v1(4236.47,724.38)
  Top Layer w10: U1.R16@4019.57,941.85 v1(4035.32,926.1)
  SIG 1 w4.75: v1(4035.32,926.1) 4037.75,923.67 4151.15,923.67 4239.59,835.24 4239.59,733.79 4239,733.2 4239,726.92 v1(4236.47,724.38)
AM263_EQEP0_A: R328.1 U1.B14 | length 3715.4
  Top Layer w5.3: U1.B14@3956.58,1351.3 3973.55,1368.27 3973.55,1388.81 3995.2,1410.46 3995.2,1464.6 4033.75,1503.15 4033.75,1688.08 4169.83,1824.16 4724.16,1824.16 4755.96,1855.96 5222.2,1855.96 v1(5259.51,1818.66)
  Bottom Layer w5.3: v1(5259.51,1818.66) 5228.17,1850 5195,1850 5167.5,1822.5 5167.5,1612 5204.25,1575.25 5204.25,1328.63 5228.38,1304.5 5228.38,1230 5301.68,1156.71 5301.68,867.97 5228.7,795 5228.7,750 5182.22,703.52 5182.22,332.77 5250,264.99 5250,96.38 5271.38,75 R328.1@5301.38,75
AM263_EQEP0_A_R: R328.2 U43.1 | length 277.2
  Bottom Layer w5.3: R328.2@5348.62,75 5524.13,75 5574.13,125 U43.1@5574.13,155.98
AM263_EQEP0_B: R329.1 U1.A14 | length 3726.7
  Top Layer w5.3: U1.A14@3956.58,1382.8 3956.58,1384.99 3984.6,1413.01 3984.6,1468.99 4023.15,1507.54 4023.15,1692.47 4165.44,1834.76 4716.52,1834.76 4748.32,1866.56 5243.44,1866.56 5279.38,1830.62 5279.38,1788.54 v1(5259.51,1768.66)
  Bottom Layer w5.3: v1(5259.51,1768.66) 5239.98,1788.18 5239.98,1816.52 5218.32,1838.18 5201.42,1838.18 5181.5,1818.26 5181.5,1699.88 5222.5,1658.88 5222.5,1334.24 5279.52,1277.22 5279.52,1226.22 5312.28,1193.47 5312.28,838.75 5268.53,795 5268.53,752.23 5192.82,676.53 5192.82,337.16 5260.6,269.38 5260.6,266.68 5261.17,266.11 5261.17,153.83 5279.91,135.09 R329.1@5301.38,135.09
AM263_EQEP0_B_R: R329.2 U43.3 | length 213.4
  Bottom Layer w5.3: R329.2@5348.62,135.09 5399.09,135.09 5455.41,191.41 U43.3@5538.7,191.41
AM263_EQEP0_INDEX: R330.1 U1.D11 | length 3586.3
  Top Layer w10: U1.D11@3862.09,1288.31 v1(3877.84,1304.06)
  SIG 1 w4: v1(3877.84,1304.06) 3894.34,1320.55 3894.34,1343.12 3910.09,1358.87 3910.09,1414.29
  SIG 1 w4.75: 3910.09,1414.29 3910.09,1501.49 3901.4,1510.18 3901.4,1598.41 3953.46,1650.48 3953.46,1744.32 3915.15,1782.62 3915.15,1923.92 3950.58,1959.35 4002.94,1959.35 4018.98,1943.31 4018.98,1918.05 4116.01,1821.01 4116.01,1767.44 4174.9,1708.55 4228.8,1708.55 4239.67,1697.68 4296.89,1697.68 4487.65,1506.92 4538.36,1506.92 4635.28,1410 4654.74,1410 4679.81,1384.94 4679.81,1347.98 4730.92,1296.87 4874.31,1296.87 4881.78,1289.4 4945.95,1289.4 4975.26,1318.71 5047.28,1318.71 5100.07,1371.5 5262.15,1371.5 v1(5269.65,1364)
  Bottom Layer w5.3: R330.1@5229.44,397.13 5229.44,421.97 5289.73,482.26 5289.73,611.02 5359.88,681.17 5359.88,860.04 5382.23,882.4 5412.4,882.4 5424.59,894.59 5424.59,1037.74 5435,1048.15 5435,1084.57 5413.5,1106.07 5413.5,1165.36 5382.23,1196.63 5382.23,1222.76 5269.65,1335.35 v1(5269.65,1364)
AM263_EQEP0_INDEX_R: R330.2 U43.4 | length 435.2
  Bottom Layer w5.3: R330.2@5229.44,349.89 5229.44,320.8 5257.23,293 5324.19,293 5347.18,270.02 5347.18,212.16 5369.34,190 5439.01,190 5460.1,211.1 U43.4@5538.7,211.1
AM263_EQEP0_STROBE: R331.1 U1.C12 | length 3559.5
  Top Layer w10: U1.C12@3893.59,1319.8 v1(3909.34,1335.55)
  SIG 1 w4: v1(3909.34,1335.55) 3925.83,1352.05 3925.83,1414.29
  SIG 1 w4.75: 3925.83,1414.29 3925.83,1499.95 3911.45,1514.34 3911.45,1594.25 3963.51,1646.32 3963.51,1748.48 3925.2,1786.79 3925.2,1919.76 3954.74,1949.3 3993.83,1949.3 4008.93,1934.21 4008.93,1913.89 4105.96,1816.85 4105.96,1763.28 4170.74,1698.5 4222.99,1698.5 4233.86,1687.63 4292.73,1687.63 4484.49,1495.87 4531.12,1495.87 4610.15,1416.84 4610.15,1399.73 4723.06,1286.82 4870.15,1286.82 4877.61,1279.35 4950.12,1279.35 4979.43,1308.66 5051.44,1308.66 5097.78,1355 5236.5,1355 5249,1342.5 5298.5,1342.5 v1(5309.5,1353.5)
  Bottom Layer w5.3: R331.1@5277.45,397.13 5277.45,442.72 5304.1,469.37 5304.1,610.4 5370.48,676.78 5370.48,815.42 5435.19,880.14 5435.19,906.89 5465.38,937.08 5465.38,1229.97 5405.35,1290 5344.5,1290 5309.5,1325 v1(5309.5,1353.5)
AM263_EQEP0_STROBE_R: R331.2 U43.5 | length 382
  Bottom Layer w5.3: R331.2@5277.45,349.89 5277.45,331.1 5303.54,305 5330,305 5361.17,273.83 5361.17,213.16 5373.5,200.83 5434.84,200.83 5464.8,230.78 U43.5@5538.7,230.78
AM263_EQEP2_A: R332.1 U1.B13 | length 4078.1
  Top Layer w4: U1.B13@3925.09,1351.3 3940.83,1367.05 3940.83,1387.93
  Top Layer w5.3: 3940.83,1387.93 3972.4,1419.5 3972.4,1471.79 4012.55,1511.93 4012.55,1696.86 4161.05,1845.36 4705.36,1845.36 4737.16,1877.16 5247.84,1877.16 5289.98,1835.02 5289.98,1788.18 v1(5309.51,1768.66)
  Bottom Layer w5.3: v1(5309.51,1768.66) 5310.4,1768.66 5349.66,1729.4 5415.42,1729.4 5504.22,1818.2 5734.35,1818.2 5794.52,1758.03 5794.52,1646.1 5736.23,1587.8 5736.23,1427.78 5794.52,1369.49 5794.52,1226.91 5787.86,1220.25 5787.86,1219.97 5744.4,1176.5 5744.4,1097.83 5694.68,1048.11 5591.4,1048.11 5445.79,902.5 5445.79,735.68 5413.06,702.96 5413.06,478.39 5382.77,448.1 5338.15,448.1 5327.45,437.4 R332.1@5327.45,397.13
AM263_EQEP2_A_R: R332.2 U43.6 | length 266.9
  Bottom Layer w5.3: R332.2@5327.45,349.89 5327.45,325.16 5352.6,300 5449.54,300 5499.07,250.47 U43.6@5538.7,250.47
AM263_EQEP2_B: R333.1 U1.A13 | length 4039
  Top Layer w4: U1.A13@3925.09,1382.8 3925.09,1392.08
  Top Layer w5.3: 3925.09,1392.08 3956.58,1423.58 3956.58,1470.96 3999.4,1513.78 3999.4,1698.71 4156.66,1855.96 4699.21,1855.96 4731.01,1887.76 5258.54,1887.76 5309.51,1836.79 v1(5309.51,1818.66)
  Bottom Layer w5.3: v1(5309.51,1818.66) 5335,1793.17 5335,1765.56 5351.42,1749.14 5420.16,1749.14 5499.83,1828.8 5738.74,1828.8 5805.12,1762.42 5805.12,1641.71 5746.83,1583.41 5746.83,1432.17 5805.12,1373.88 5805.12,1222.24 5755,1172.11 5755,1038.76 5721.24,1005 5614.98,1005 5579.67,969.69 5561.6,969.69 5484.84,892.93 5484.84,727.99 5426.85,670 5426.85,475.45 5377.45,426.05 R333.1@5377.45,397.13
AM263_EQEP2_B_R: R333.2 U43.7 | length 207.4
  Bottom Layer w5.3: R333.2@5377.45,349.89 5377.45,327.55 5394.4,310.6 5453.93,310.6 5494.38,270.15 U43.7@5538.7,270.15
AM263_EQEP2_INDEX: R334.1 U1.A12 | length 4237.5
  Top Layer w5.3: U1.A12@3893.59,1382.8 3893.59,1391.19 3923.85,1421.45 3923.85,1468.2 3977.48,1521.84 3977.48,1706.77 4147.88,1877.16 4679.53,1877.16 4711.33,1908.96 5296.81,1908.96 5379.48,1826.3 5379.48,1788.63 v1(5359.51,1768.66)
  Bottom Layer w5.3: v1(5359.51,1768.66) 5402.86,1768.66 5481.51,1847.31 5742.69,1847.31 5830,1760 5830,1676.8 5844.52,1662.28 5844.52,1637.83 5907.5,1574.85 5907.5,1027.26 5860.24,980 5604.97,980 5584.06,959.09 5565.99,959.09 5495.44,888.54 5495.44,702.96 5437.45,644.97 5437.45,446.35 5428.06,436.97 R334.1@5428.06,397.13
AM263_EQEP2_INDEX_R: R334.2 U43.8 | length 147.2
  Bottom Layer w5.3: R334.2@5428.06,349.89 5428.06,330 5436.86,321.2 5458.32,321.2 5489.68,289.84 U43.8@5538.7,289.84
AM263_EQEP2_STROBE: R335.1 U1.B12 | length 4192.9
  Top Layer w4: U1.B12@3893.59,1351.3 3910,1367.71 3910,1385
  Top Layer w5.3: 3910,1385 3910,1391.99 3940,1421.99 3940,1469.37 3988.08,1517.45 3988.08,1702.38 4152.27,1866.56 4687.63,1866.56 4719.43,1898.36 5279.8,1898.36 v1(5359.51,1818.66)
  Bottom Layer w5.3: v1(5359.51,1818.66) 5420.14,1818.66 5466.48,1865 5750,1865 5843.5,1771.5 5843.5,1679.5 5855.48,1667.52 5855.48,1650.65 5921,1585.12 5921,1025.46 5865,969.46 5865,969.4 5609.36,969.4 5588.45,948.49 5570.38,948.49 5510,888.11 5510,702.53 5448.05,640.58 5448.05,469.67 5478.01,439.71 R335.1@5478.01,397.13
AM263_EQEP2_STROBE_R: R335.2 U43.9 | length 91.1
  Bottom Layer w5.3: R335.2@5478.01,349.89 5478.01,326.51 5495,309.52 U43.9@5538.7,309.52
AM263_EXT_REFCLK0: TP2.1 U1.P2 | length 637.5
  Top Layer w5.3: v1(3060,926.1) 3060,866.22 TP2.1@3061.79,864.43 ; v1(3298.62,925.4) 3311.89,938.67 3493.09,938.67 3510.79,956.37 3561.66,956.37 U1.P2@3578.63,973.35
  SIG 1 w5.3: v1(3060,926.1) 3065.9,932 3143.46,932 3172.83,961.37 3223.09,961.37 3234.52,949.94 3234.52,937.86 3246.99,925.4 v1(3298.62,925.4)
AM263_FSIRX1_CLK: J23.1 U1.E1 | length 2160.2
  Top Layer w4: 3515.64,1256.81 U1.E1@3547.13,1256.81
  Top Layer w5.3: J23.1@3404.17,1950 3331,1950 3213,1832 3213,1524 3147.98,1458.98 3147.98,1319.46 3170.54,1296.89 3255.82,1296.89 3285.71,1267 3439.5,1267 3449.69,1256.81 3515.64,1256.81
  Bottom Layer w5.3: v1(2975.61,1290) 2976.32,1290.71 2976.32,1418.09 3293.73,1735.5 3427.61,1735.5 3452.05,1759.94 3452.05,1902.13 J23.1@3404.17,1950
AM263_FSIRX1_DATA0: J23.5 U1.F3 | length 1782.6
  Top Layer w10: v1(3594.38,1241.06) U1.F3@3610.12,1225.32
  SIG 1 w4: 3515.64,1241.06 v1(3594.38,1241.06)
  SIG 1 w4.75: v1(2935,1290) 2953.56,1271.44 2966.94,1271.44 2967.63,1270.75 3038.25,1270.75 3052.5,1256.5 3125.39,1256.5 3140.82,1241.06 3515.64,1241.06
  Bottom Layer w5.3: v1(2935,1290) 2955,1270 2985,1270 3000,1285 3000,1426.78 3297.22,1724 3434,1724 3470,1760 3470,1825.78 3587.73,1943.5 3597.67,1943.5 J23.5@3604.17,1950
AM263_FSIRX1_DATA1: J23.7 U1.F4 | length 1770.2
  Top Layer w5.3: v1(3167.5,1347) 3167.5,1461.5 3223.6,1517.6 3223.6,1822 3307.1,1905.5 3659.67,1905.5 J23.7@3704.17,1950
  Top Layer w10: v1(3625.87,1241.06) U1.F4@3641.62,1225.32
  SIG 1 w4: 3515.64,1257.18 3609.75,1257.18 v1(3625.87,1241.06)
  SIG 1 w4.75: v1(3167.5,1347) 3156.21,1335.71 3081.21,1335.71 3071,1325.5 3071,1290 3081.5,1279.5 3141,1279.5 3163.32,1257.18 3515.64,1257.18
AM263_FSITX1_CLK: J23.2 R54.1 | length 1614.7
  Top Layer w5.3: R54.1@3190,1317.26 3190,1369 3180,1379 3180,1456.5 3239,1515.5 3239,1817.6 3314.9,1893.5 3708.49,1893.5 3747.18,1932.19 3747.18,2081.32 3717,2111.5 3465.67,2111.5 J23.2@3404.17,2050
AM263_FSITX1_CLK_R: R54.2 U1.E4 | length 479.6
  Top Layer w5.3: R54.2@3229.37,1317.26 3231.34,1317.26 3249,1334.92 v1(3249,1354.5)
  Top Layer w10: v1(3625.87,1272.56) U1.E4@3641.62,1256.81
  SIG 1 w4: 3516.64,1288.5 3609.93,1288.5 v1(3625.87,1272.56)
  SIG 1 w4.75: v1(3249,1354.5) 3288,1315.5 3458.5,1315.5 3485.5,1288.5 3516.64,1288.5
AM263_FSITX1_DATA0: J23.6 R57.1 | length 1115.8
  Top Layer w5.3: R57.1@3190,1274.26 3170.24,1274.26 3135.36,1309.14 3135.36,1461.35 3202.4,1528.39 3202.4,1838.9 3357,1993.5 3547.67,1993.5 J23.6@3604.17,2050
AM263_FSITX1_DATA0_R: R57.2 U1.F2 | length 369.5
  Top Layer w4: 3515.64,1242.05 3561.9,1242.05 U1.F2@3578.63,1225.32
  Top Layer w5.3: R57.2@3229.37,1274.26 3258.74,1274.26 3290.95,1242.05 3515.64,1242.05
AM263_FSITX1_DATA1: J23.8 R58.1 | length 1404.9
  Top Layer w5.3: R58.1@3190,1231.26 3145.39,1231.26 3118.16,1258.5 3104.44,1258.5 3075.16,1287.78 3075.16,1416.14 3190.7,1531.68 3190.7,1844.2 3353,2006.5 3532,2006.5 3553,2027.5 3553,2074 3573,2094 3660.17,2094 J23.8@3704.17,2050
AM263_FSITX1_DATA1_R: R58.2 U1.G2 | length 365.1
  Top Layer w4: 3515.64,1209.57 3562.88,1209.57 U1.G2@3578.63,1193.82
  Top Layer w5.3: R58.2@3229.37,1231.26 3231.74,1231.26 3249.78,1213.22 3499.19,1213.22 3502.3,1210.12 3502.3,1209.57 3515.64,1209.57
AM263_I2C1_SCL: J5/J7.49 R175.1 U1.D7 U16.6 U48.15 | length 9416.8
  Top Layer w5.3: U48.15@2052.72,1495 2084.14,1495 2093.57,1485.56 2093.57,1429.46 2135.7,1387.34 2271.11,1387.34 2338.06,1320.38 2421.5,1320.38 2465,1363.89 2465,1557.62 2540.58,1633.2 2540.58,1870.21 2594.07,1923.69 2594.07,1949.07 v1(2625,1980) ; J5/J7.49@4904.17,250 4904.17,160.51 R175.1@4903.31,159.65 4935.35,159.65 4970,125 4970,85 4988.58,66.42 5469.31,66.42 5517.89,115 5563.27,115 5655,206.73 v1(5655,421.38) 5616.38,460 5488.71,460 5460.6,488.11 5460.6,571.98 5477.76,589.14 U16.6@5545.51,589.14
  Top Layer w10: v1(3720.36,1304.06) U1.D7@3736.11,1288.31
  SIG 1 w4: v1(3720.36,1304.06) 3735.36,1319.06 3735.36,1414.29
  SIG 1 w4.75: 3735.36,1414.29 3735.36,1688.14 3764.25,1717.03 3764.25,1805.16 3769.25,1810.16 3769.25,1854.65 3875.05,1960.45 v1(3875.05,2090.05)
  Bottom Layer w5.3: v1(2625,1980) 2810.5,1980 2828,1997.5 2908,1997.5 2946,1959.5 3242.04,1959.5 3383.19,2100.65 3861.68,2100.65 3872.28,2090.05 v1(3875.05,2090.05) 3912.35,2090.05 3964.31,2038.09 4004.25,2038.09 4156.88,2190.72 5707.48,2190.72 5882.72,2015.49 5882.72,1854.22 5933.8,1803.13 6029.61,1803.13 6072.85,1759.89 6072.85,1659.68 6083.8,1648.73 6083.8,1316.2 6112.62,1287.38 6112.62,976.63 5984.47,848.48 5905.04,848.48 5827.42,926.1 5728.23,926.1 5682.27,880.14 5682.27,819.31 5749.4,752.17 5749.4,515.78 v1(5655,421.38)
AM263_I2C1_SDA: J5/J7.50 R176.1 U1.C8 U16.5 U48.2 | length 8634.5
  Top Layer w5.3: U48.2@2267.28,1495 2353.98,1495 2515,1656.02 2515,1875.92 2569.22,1930.14 2569.22,2003.42 v1(2605.48,2039.68) ; J5/J7.50@5004.17,250 R176.1@5004.17,159.65 5409.65,159.65 5515,265 5515,334.61 5570,389.61 v1(5570,420) 5545,445 5486.14,445 5450,481.14 5450,625 5464.14,639.14 U16.5@5545.51,639.14
  Top Layer w10: v1(3751.86,1335.55) U1.C8@3767.61,1319.8
  SIG 1 w4: v1(3751.86,1335.55) 3775.62,1359.32 3775.62,1425.57
  SIG 1 w4.75: 3775.62,1425.57 3775.62,1453.13 3753.75,1475 3753.75,1689.45 3774.3,1710 3774.3,1801 3779.3,1806 3779.3,1845.42 3930,1996.12 v1(3930,2024.75)
  Bottom Layer w5.3: v1(2605.48,2039.68) 2605.48,1969.13 2628.11,1946.5 3244.03,1946.5 3387.58,2090.05 3838.15,2090.05 3857.68,2070.53 3916.69,2070.53 3930,2057.21 v1(3930,2024.75) 4005.9,2024.75 4161.27,2180.12 5703.09,2180.12 5865,2018.21 5865,1854.37 5926.84,1792.53 5998.02,1792.53 6025,1765.56 6025,1672.52 6073.2,1624.32 6073.2,1311.78 6102.02,1282.96 6102.02,981.02 5980.08,859.08 5909.44,859.08 5830.92,937.6 5724.74,937.6 5665.6,878.46 5665.6,793.26 5738.8,720.06 5738.8,543.9 5614.9,420 v1(5570,420)
AM263_I2C3_SCL: J1/J3.9 R55.1 U1.H2 U35.2 | length 3534.8
  Top Layer w4: 3515.64,1177.69 3563.27,1177.69 U1.H2@3578.63,1162.32
  Top Layer w5.3: U35.2@1771.58,1462.4 1771.58,1392.87 1860,1304.45 1860,1226.21 1972.4,1113.81 1972.4,1015.62 1994.17,993.85 1995.98,993.85 1996.13,993.7 v1(2007.95,993.7) ; R55.1@2404.17,170 J1/J3.9@2404.17,250 ; v1(3180,1159.39) 3184.39,1155 3468.45,1155 3491.13,1177.69 3515.64,1177.69
  SIG 1 w4.75: v1(2007.95,993.7) 1967.11,1034.54 1967.11,1146.3 2060.3,1239.49 2233.05,1239.49 2263.97,1270.41 2864.95,1270.41 2896.36,1239 3002,1239 3059,1182 3126.24,1182 3148.86,1159.39 v1(3180,1159.39)
  Bottom Layer w5.3: v1(2007.95,993.7) 2055.85,945.8 2055.85,740.43 2070.48,725.81 2070.48,574.87 2089.88,555.47 2089.88,530.6 2184.8,435.67 2315.18,435.67 2360,390.85 2360,294.17 J1/J3.9@2404.17,250
AM263_I2C3_SDA: J1/J3.10 R56.1 U1.G3 U35.3 | length 3598.3
  Top Layer w5.3: U35.3@1797.17,1462.4 1797.17,1392.83 1840,1350 1980.45,1350 1999.67,1330.78 1999.67,1206.08 v1(1990,1196.41) ; R56.1@2504.17,170 J1/J3.10@2504.17,250
  Top Layer w10: v1(3594.38,1209.57) U1.G3@3610.12,1193.82
  SIG 1 w4.75: v1(1990,1196.41) 2043.74,1250.15 2227.14,1250.15 2257.45,1280.46 2879.35,1280.46 2909.85,1249.95 3015.1,1249.95 3034.05,1231 3104,1231 3124.42,1210.58 3593.37,1210.58 v1(3594.38,1209.57)
  Bottom Layer w5.3: v1(1990,1196.41) 2080.2,1196.41 2120.2,1156.41 2120.2,1031.38 2067.39,978.57 2067.39,743.89 2119.88,691.4 2119.88,618.02 2100.48,598.62 2100.48,535.88 2190.09,446.27 2393.73,446.27 2463.14,376.86 2463.14,291.04 J1/J3.10@2504.17,250
AM263_ICSSM_MII0_COL: R207.1 R219.2 R231.2 U37.45 U49.11 | length 2483
  Top Layer w5.3: v1(5835,786.84) U49.11@5877.2,786.84 ; R207.1@6674.39,1876.46 v1(6700,1876.46)
  SIG 1 w4.75: v1(5835,786.84) 5881.84,740 6304.59,740 6305.65,741.06 6350.52,741.06 6424.46,815 6531.49,815 6578.11,768.37 6578.11,738.69 6589.88,726.92 6710,726.92 6735.75,752.67 6735.75,981.83 6748.64,994.71 6748.64,1033.27 6713.34,1068.57 6713.34,1215.64 6765.6,1267.91 6765.6,1580.48 6748.64,1597.44 6748.64,1759.67 6700,1808.31 v1(6700,1876.46)
  Bottom Layer w5.3: U37.45@6674.39,1803.9 6674.52,1804.03 6674.52,1876.32 R219.2@6674.39,1876.46 v1(6700,1876.46) R231.2@6700,1985
AM263_ICSSM_MII0_CRS: U49.14
AM263_ICSSM_MII0_RXCLK: R196.1 U23.32 | length 2186.3
  Top Layer w5.3: U23.32@4892.17,1495.87 v1(5026.97,1495.87)
  SIG 1 w4.75: v1(5026.97,1495.87) 5052.52,1495.87 5130,1573.35 5130,1630 5148.88,1648.88 5190,1648.88 5205,1633.88 5205,1547.01 5218.7,1533.31 5272.43,1533.31 5290.93,1551.81 5290.93,1625.68 5314.12,1648.88 5351.12,1648.88 5368.7,1631.3 5368.7,1550.78 5381.13,1538.35 5447.26,1538.35 5458.38,1549.47 5458.38,1699.63 5542.5,1783.75 6128.06,1783.75 6213.36,1698.45 v1(6213.36,1620.91)
  Bottom Layer w5.3: v1(6213.36,1620.91) 6213.36,1644.73 6263.67,1695.04 R196.1@6351.89,1695.04
AM263_ICSSM_MII0_RXCLK_R: R196.2 U37.32 | length 94.1
  Bottom Layer w5.3: R196.2@6399.14,1695.04 6403.66,1699.57 U37.32@6491.32,1699.57
AM263_ICSSM_MII0_RXD0: R198.1 R203.1 R215.2 U23.41 | length 2259.9
  Top Layer w5.3: U23.41@4817.36,1629.73 4817.36,1674.62 4866.61,1723.86 v1(4893.56,1723.86) ; R203.1@6275,1752.65 6307.35,1752.65 v1(6315,1745)
  SIG 1 w4.75: v1(4893.56,1723.86) 4932.42,1685 5075.67,1685 5114.25,1723.58 5114.25,1750.62 5213.63,1850 5743.81,1850 5759.81,1834 5996.48,1834 6042.48,1880 6140,1880 6172.02,1912.02 6172.02,1976.07 6190.95,1995 6354.95,1995 6390,1959.95 6390,1773.91 6361.09,1745 v1(6315,1745)
  Bottom Layer w5.3: R215.2@6274.92,1752.65 6305.55,1752.65 6313.2,1745 v1(6315,1745) v1(6315,1745) R198.1@6351.89,1745.04
AM263_ICSSM_MII0_RXD0_R: R198.2 U37.33 | length 102.9
  Bottom Layer w5.3: R198.2@6399.14,1745.04 6434.21,1745.04 6460,1719.25 U37.33@6491.32,1719.25
AM263_ICSSM_MII0_RXD1: R199.1 R204.1 R216.2 U23.39 | length 2182.3
  Top Layer w5.3: U23.39@4856.73,1629.73 4856.73,1664.99 4861.74,1670 v1(4893.56,1670) ; v1(6274.92,1798.96) 6275,1799.04 R204.1@6275,1830.96
  SIG 1 w4.75: v1(4893.56,1670) 5074.88,1670 5195.38,1790.5 5386.09,1790.5 5419.54,1823.95 6004.95,1823.95 6049.09,1868.09 6142.3,1868.09 6182.07,1907.86 6182.07,1970.68 6196.35,1984.95 6350.79,1984.95 6379.95,1955.79 6379.95,1809.66 6345.29,1775 6298.88,1775 v1(6274.92,1798.96)
  Bottom Layer w5.3: v1(6274.92,1798.96) 6275,1799.04 R216.2@6275,1830.96 6275.11,1830.85 6335,1830.85 6351.89,1813.96 R199.1@6351.89,1795.04
AM263_ICSSM_MII0_RXD1_R: R199.2 U37.34 | length 126.8
  Bottom Layer w5.3: R199.2@6399.14,1795.04 6399.18,1795 6425.16,1795 6438.01,1782.15 6438.01,1762.74 6461.81,1738.94 U37.34@6491.32,1738.94
AM263_ICSSM_MII0_RXD2: R200.1 R210.1 R222.2 U23.38 | length 2143.2
  Top Layer w5.3: U23.38@4892.17,1613.98 4964.13,1613.98 v1(4983.82,1594.29) ; R210.1@6383.01,1989.35 6411.65,1989.35 v1(6411.73,1989.27)
  SIG 1 w4.75: v1(4983.82,1594.29) 5018.16,1594.29 5173.28,1749.41 5367.48,1749.41 5431.97,1813.9 6013.95,1813.9 6058.09,1858.04 6146.47,1858.04 6165.12,1876.69 6228.31,1876.69 6255.67,1849.33 6255.67,1760.83 6298.88,1717.62 6362.62,1717.62 6411.73,1766.73 v1(6411.73,1989.27)
  Bottom Layer w5.3: R200.1@6406.28,1918.62 6397.12,1927.78 6397.12,1950.5 6383.01,1964.61 R222.2@6383.01,1989.35 6411.65,1989.35 v1(6411.73,1989.27)
AM263_ICSSM_MII0_RXD2_R: R200.2 U37.35 | length 159.3
  Bottom Layer w5.3: R200.2@6406.28,1871.38 6406.28,1833.72 6448.61,1791.39 6448.61,1781.98 6471.97,1758.62 U37.35@6491.32,1758.62
AM263_ICSSM_MII0_RXD3: R201.1 R211.1 R223.2 U23.36 | length 2186
  Top Layer w5.3: U23.36@4892.17,1574.61 4964.13,1574.61 v1(4983.82,1554.92) ; R211.1@6443.01,1989.35 v1(6471.73,1989.27) v1(6471.73,1989.27)
  SIG 1 w4.75: v1(4983.82,1554.92) 4994.92,1554.92 5141.14,1701.14 5347.63,1701.14 5450.34,1803.85 6018.14,1803.85 6062.28,1847.99 6147.02,1847.99 6300.01,1695 6364.04,1695 6444.47,1775.43 6444.47,1999.47 6455,2010 6467.22,2010 6471.73,2005.49 v1(6471.73,1989.27)
  Bottom Layer w5.3: R201.1@6456.28,1918.62 6456.28,1943.72 6443.01,1956.99 R223.2@6443.01,1989.35 v1(6471.73,1989.27) v1(6471.73,1989.27)
AM263_ICSSM_MII0_RXD3_R: R201.2 U37.36 | length 116.2
  Bottom Layer w5.3: R201.2@6456.28,1871.38 6456.28,1798.71 6476.68,1778.31 U37.36@6491.32,1778.31
AM263_ICSSM_MII0_RXDV: R197.1 R205.1 R217.2 U23.34 | length 2223.6
  Top Layer w5.3: U23.34@4892.17,1535.24 4964.74,1535.24 v1(4984.43,1515.55) ; R205.1@6506.28,1989.43 6534.92,1989.43 v1(6535,1989.35)
  SIG 1 w4.75: v1(4984.43,1515.55) 5159.93,1691.06 5351.76,1691.06 5454.5,1793.8 6185.09,1793.8 6294.37,1684.51 6294.37,1663.83 6305.65,1652.56 6352.8,1652.56 6475.75,1775.51 6475.75,1890 6485.75,1900 6520,1900 6545,1925 6545,1979.35 v1(6535,1989.35)
  Bottom Layer w5.3: R197.1@6506.28,1918.62 R217.2@6506.28,1989.43 6534.92,1989.43 v1(6535,1989.35)
AM263_ICSSM_MII0_RXDV_R: R197.2 U37.38 | length 80
  Bottom Layer w5.3: R197.2@6506.28,1871.38 6506.28,1852.66 6536.59,1822.35 U37.38@6536.59,1803.9
AM263_ICSSM_MII0_RXER: R206.1 R218.2 R235.2 U37.46 U49.2 | length 2661.3
  Top Layer w5.3: v1(5574.59,914.8) 5600.18,889.2 U49.2@5652.8,889.2 ; v1(6694.07,1779.98) 6694.07,1810.03 6724.04,1840 6785,1840 6795,1850 6795,1874.79 R206.1@6796.28,1876.06 v1(6822.14,1876.06) R218.2@6848,1876.06
  SIG 1 w4.75: v1(5574.59,914.8) 5854.89,914.8 5986.39,783.3 6199.35,783.3 6216.09,800.03 6282.75,800.03 6307.03,775.75 6367.49,775.75 6416.79,825.05 6535.65,825.05 6593.6,767.1 6667.1,767.1 6719.25,819.25 6719.25,992.92 6703.29,1008.88 6703.29,1224.29 6755.55,1276.55 6755.55,1576.31 6735.75,1596.11 6735.75,1738.3 v1(6694.07,1779.98)
  Bottom Layer w5.3: v1(6694.07,1779.98) U37.46@6694.07,1803.9 ; v1(6822.14,1876.06) 6822.77,1876.69 R235.2@6848,1876.69
AM263_ICSSM_MII0_RXLINK: R208.1 R220.2 R233.2 U37.47 U49.5 | length 2777.1
  Top Layer w5.3: v1(5610.59,812.43) U49.5@5652.8,812.43 ; R208.1@6729.39,1876.46 v1(6758,1876.46)
  SIG 1 w4.75: v1(5610.59,812.43) 5689.53,812.43 5697.98,803.98 5737.42,803.98 5824.99,716.41 5881.68,716.41 5895.21,729.95 6278.26,729.95 6305.65,702.56 6329.24,702.56 6427.29,800.6 6531.62,800.6 6544.25,787.97 6544.25,768.34 6534.22,758.31 6534.22,738.69 6556.04,716.87 6741.87,716.87 6785,760 6785,975.92 6766.98,993.94 6766.98,1041.66 6723.39,1085.25 6723.39,1208.39 6775.65,1260.65 6775.65,1599.53 6765,1610.18 6765,1757.52 6730,1792.52 6730,1848.46 v1(6758,1876.46)
  Bottom Layer w5.3: U37.47@6713.76,1803.9 6713.76,1829.37 6729.39,1845 R220.2@6729.39,1876.46 v1(6758,1876.46) 6794.76,1876.46 R233.2@6795,1876.69
AM263_ICSSM_MII0_TXCLK: U23.19 U37.29 | length 2245
  Top Layer w5.3: v1(4797.68,1195.01) 4817.36,1214.69 U23.19@4817.36,1283.27
  SIG 1 w4.75: v1(4797.68,1195.01) 4816.93,1214.26 4816.93,1237.36 4835.53,1255.97 4858.36,1255.97 4865.13,1249.2 5026.48,1249.2 5100.59,1323.32 5271.68,1323.32 5295,1300 5497.08,1300 5574.45,1377.37 6203.73,1377.37 6221,1360.1 6329.33,1360.1 6364.23,1395 6412.71,1395 6516.08,1498.37 6516.08,1590.42 6483.53,1622.97 6461.5,1622.97 v1(6445,1606.47)
  Bottom Layer w5.3: v1(6445,1606.47) 6445,1619.87 6465.64,1640.51 U37.29@6491.32,1640.51
AM263_ICSSM_MII0_TXD0: U23.29 U37.28 | length 2238.6
  Top Layer w5.3: U23.29@4892.17,1436.81 v1(4933.82,1436.81)
  SIG 1 w4.75: v1(4933.82,1436.81) 4953.26,1456.25 5543.75,1456.25 5582.43,1417.57 6020,1417.57 6043.31,1440.89 6043.31,1533.31 6060,1550 6090.94,1550 6104.93,1536.01 6104.93,1437.02 6114.98,1426.97 6141.97,1426.97 6155,1440 6155,1575.32 6172.02,1592.34 6325.23,1592.34 6477.9,1745 6514.23,1745 6520,1739.23 v1(6520,1615)
  Bottom Layer w5.3: U37.28@6491.32,1620.83 6514.17,1620.83 v1(6520,1615)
